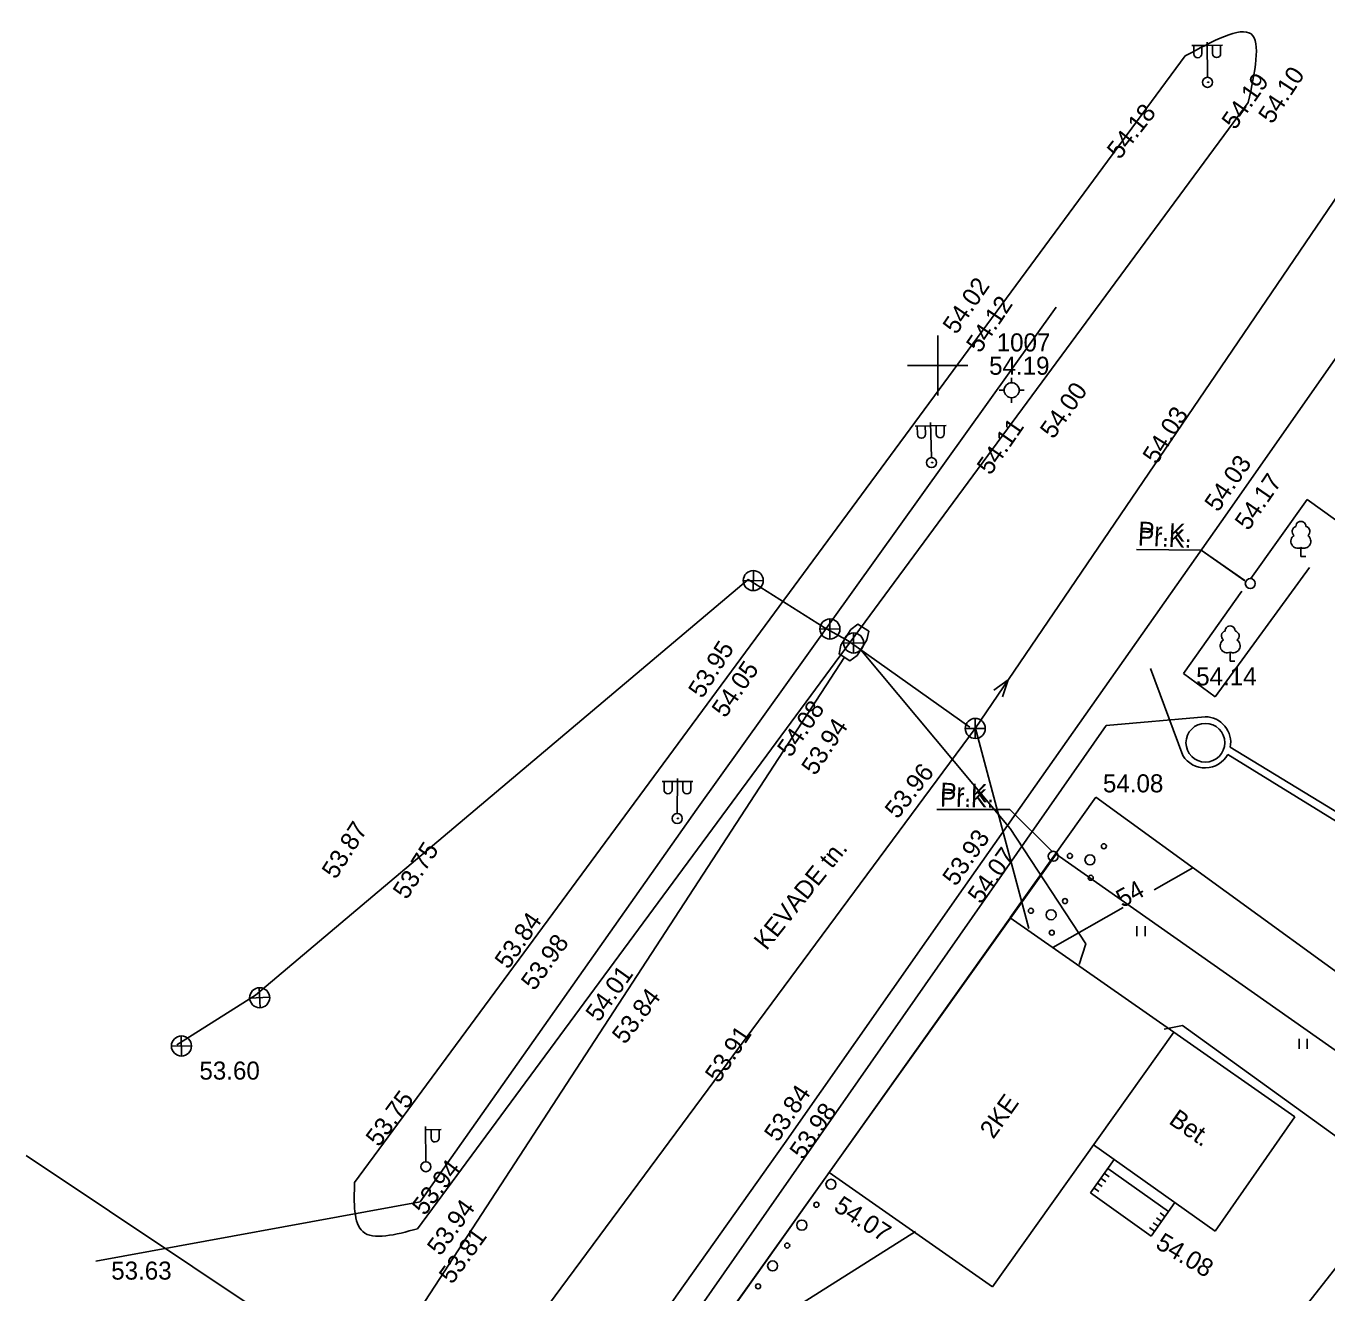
# Model space of a CAD drawing. Extents: x -2270 to -2134, y 846 to 969.
# Drawn here: x -2257.8 to -2193, y 905.3 to 968.5 of the extents above; entities that cross this region are included whole.
import ezdxf

# ---------------------------------------------------------------- set-up
doc = ezdxf.new("R2010")
doc.units = 0
for name, color, linetype in [('Level 11', 7, 'Continuous'), ('Level 12', 7, 'Continuous'), ('Level 15', 7, 'Continuous'), ('Level 16', 7, 'Continuous'), ('Level 18', 7, 'Continuous'), ('Level 19', 7, 'Continuous'), ('Level 21', 7, 'Continuous'), ('Level 29', 7, 'Continuous'), ('Level 31', 7, 'Continuous'), ('Level 32', 7, 'Continuous'), ('Level 4', 7, 'Continuous'), ('Level 45', 7, 'Continuous'), ('Level 6', 7, 'Continuous'), ('Level 7', 7, 'Continuous'), ('Level 8', 7, 'Continuous'), ('Level 9', 7, 'Continuous')]:
    doc.layers.add(name, color=color, linetype=linetype)

msp = doc.modelspace()

# ---------------------------------------------------------------- linework, layer by layer
at = {"layer": 'Level 11'}
for p, q in [((-2221.556, 941.341), (-2221.573, 940.341)), ((-2222.064, 940.85), (-2221.065, 940.832)), ((-2217.74, 938.926), (-2217.746, 937.926)), ((-2218.243, 938.429), (-2217.243, 938.423)), ((-2216.562, 938.229), (-2216.565, 937.229)), ((-2217.063, 937.731), (-2216.063, 937.727)), ((-2210.494, 933.965), (-2210.495, 932.965)), ((-2210.994, 933.466), (-2209.994, 933.464)), ((-2246.205, 920.534), (-2246.152, 919.536)), ((-2246.678, 920.009), (-2245.679, 920.062)), ((-2250.086, 918.127), (-2250.071, 917.127)), ((-2250.578, 917.62), (-2249.579, 917.634))]:
    msp.add_line(p, q, dxfattribs=at)
for centre in [(-2221.564, 940.841), (-2217.743, 938.426), (-2216.563, 937.729), (-2210.494, 933.465), (-2246.178, 920.035), (-2250.078, 917.627)]:
    msp.add_circle(centre, 0.5, dxfattribs=at)
at = {"layer": 'Level 12'}
for p, q in [((-2198.893, 965.701), (-2198.916, 965.696)), ((-2198.914, 965.686), (-2198.916, 965.696)), ((-2198.856, 965.72), (-2198.895, 965.711)), ((-2198.895, 965.711), (-2198.891, 965.692)), ((-2198.852, 965.7), (-2198.891, 965.692)), ((-2198.856, 965.72), (-2198.852, 965.7)), ((-2212.654, 946.731), (-2212.677, 946.725)), ((-2212.675, 946.715), (-2212.677, 946.725)), ((-2212.617, 946.75), (-2212.656, 946.74)), ((-2212.656, 946.74), (-2212.652, 946.721)), ((-2212.613, 946.73), (-2212.652, 946.721)), ((-2212.617, 946.75), (-2212.613, 946.73)), ((-2199.231, 942.365), (-2202.455, 942.392)), ((-2197.055, 940.837), (-2199.231, 942.365)), ((-2225.331, 928.98), (-2225.354, 928.975)), ((-2225.352, 928.965), (-2225.354, 928.975)), ((-2225.293, 928.998), (-2225.333, 928.99)), ((-2225.333, 928.99), (-2225.329, 928.97)), ((-2225.289, 928.978), (-2225.329, 928.97)), ((-2225.293, 928.998), (-2225.289, 928.978)), ((-2208.772, 929.43), (-2212.416, 929.43)), ((-2206.655, 927.334), (-2208.772, 929.43)), ((-2237.905, 913.605), (-2237.89, 911.855)), ((-2237.903, 913.448), (-2237.135, 913.454)), ((-2237.632, 913.451), (-2237.629, 913.036)), ((-2237.232, 913.453), (-2237.229, 913.04))]:
    msp.add_line(p, q, dxfattribs=at)
for centre in [(-2196.782, 940.691), (-2206.607, 927.089), (-2237.888, 911.605)]:
    msp.add_circle(centre, 0.25, dxfattribs=at)
msp.add_arc((-2237.429, 913.038), 0.2, 180.45577, 0.45577, dxfattribs=at)
at = {"layer": 'Level 15'}
msp.add_line((-2207.825, 923.49), (-2210.493, 933.535), dxfattribs=at)
for points in [[(-2238.128, 896.128), (-2210.494, 933.465), (-2189.567, 964.235)], [(-2209.567, 935.379), (-2208.851, 935.896), (-2209.13, 935.041)]]:
    msp.add_lwpolyline(points, dxfattribs=at)
at = {"layer": 'Level 16'}
for p, q in [((-2212.369, 953.074), (-2212.369, 950.074)), ((-2213.869, 951.574), (-2210.869, 951.574)), ((-2208.681, 950.961), (-2208.681, 950.711)), ((-2209.306, 950.336), (-2209.056, 950.336)), ((-2208.681, 949.961), (-2208.681, 949.711)), ((-2208.306, 950.336), (-2208.056, 950.336)), ((-2237.916, 892.929), (-2213.477, 908.38))]:
    msp.add_line(p, q, dxfattribs=at)
msp.add_circle((-2208.681, 950.336), 0.375, dxfattribs=at)
at = {"layer": 'Level 18'}
msp.add_line((-2246.733, 891.382), (-2217.016, 937.014), dxfattribs=at)
msp.add_lwpolyline([(-2205.312, 921.696), (-2204.98, 922.729), (-2208.752, 928.473), (-2216.197, 937.392)], dxfattribs=at)
at = {"layer": 'Level 19'}
for p, q in [((-2200.024, 967.013), (-2241.447, 910.825)), ((-2196.881, 964.696), (-2238.304, 908.508)), ((-2185.903, 961.405), (-2197.926, 944.224)), ((-2197.926, 944.224), (-2211.091, 925.475)), ((-2200.146, 932.114), (-2201.752, 936.449)), ((-2230.178, 896.053), (-2203.961, 933.613)), ((-2203.961, 933.613), (-2199.031, 934.048)), ((-2211.091, 925.475), (-2220.006, 912.755)), ((-2220.006, 912.755), (-2232.856, 894.697)), ((-2232.804, 895.458), (-2257.828, 912.171))]:
    msp.add_line(p, q, dxfattribs=at)
for points in [[(-2197.783, 932.526), (-2180.783, 922.176), (-2171.133, 931.391), (-2166.861, 928.633)], [(-2197.901, 932.165), (-2180.774, 921.614), (-2171.008, 930.85), (-2167.125, 928.209)]]:
    msp.add_lwpolyline(points, dxfattribs=at)
msp.add_circle((-2199.022, 932.755), 0.966, dxfattribs=at)
for centre, radius, start, end in [((-2199.038, 932.77), 1.279, 348.99678, 89.69052), ((-2199.039, 932.805), 1.305, 211.96214, 330.64357)]:
    msp.add_arc(centre, radius, start, end, dxfattribs=at)
for points in [[(-2200.024, 967.013), (-2196.743, 968.107), (-2196.881, 964.696)], [(-2241.447, 910.825), (-2241.036, 908.365), (-2238.304, 908.508)]]:
    msp.add_spline(points, degree=3, dxfattribs=at)
at = {"layer": 'Level 21'}
for p, q in [((-2224.379, 929.446), (-2206.468, 954.486)), ((-2238.17, 909.855), (-2224.379, 929.446)), ((-2200.158, 918.652), (-2201.075, 918.46)), ((-2189.64, 911.045), (-2200.158, 918.652)), ((-2208.173, 886.648), (-2189.276, 910.702)), ((-2254.351, 906.888), (-2238.17, 909.855))]:
    msp.add_line(p, q, dxfattribs=at)
at = {"layer": 'Level 29'}
msp.add_line((-2216.836, 937.839), (-2210.772, 933.534), dxfattribs=at)
msp.add_lwpolyline([(-2250.314, 917.68), (-2246.382, 920.16), (-2221.812, 940.896), (-2218.033, 938.498), (-2216.836, 937.839)], dxfattribs=at)
at = {"layer": 'Level 31'}
msp.add_lwpolyline([(-2215.809, 938.321), (-2215.899, 937.885), (-2216.392, 937.11), (-2216.747, 936.843), (-2217.284, 937.184), (-2217.194, 937.619), (-2216.701, 938.395), (-2216.346, 938.661)], close=True, dxfattribs=at)
at = {"layer": 'Level 32'}
for p, q in [((-2199.64, 926.521), (-2201.567, 925.422)), ((-2203.125, 924.535), (-2206.628, 922.538))]:
    msp.add_line(p, q, dxfattribs=at)
at = {"layer": 'Level 45'}
for p, q in [((-2230.947, 892.878), (-2206.455, 927.192)), ((-2206.455, 927.192), (-2182.404, 910.289))]:
    msp.add_line(p, q, dxfattribs=at)
at = {"layer": 'Level 6'}
for p, q in [((-2208.75, 924.023), (-2217.784, 911.32)), ((-2208.75, 924.023), (-2217.784, 911.32)), ((-2208.75, 924.023), (-2200.602, 918.32)), ((-2200.602, 918.32), (-2209.636, 905.617)), ((-2194.555, 914.088), (-2200.602, 918.32)), ((-2198.54, 908.394), (-2194.555, 914.088)), ((-2198.54, 908.394), (-2204.598, 912.702)), ((-2204.756, 910.298), (-2203.567, 911.969)), ((-2200.861, 909.369), (-2203.887, 911.521)), ((-2217.784, 911.32), (-2209.636, 905.617)), ((-2204.164, 910.613), (-2204.408, 910.787)), ((-2203.99, 910.858), (-2204.234, 911.032)), ((-2203.816, 911.102), (-2204.061, 911.276)), ((-2201.73, 908.146), (-2204.756, 910.298)), ((-2204.338, 910.369), (-2204.582, 910.543)), ((-2201.73, 908.146), (-2200.542, 909.818)), ((-2201.209, 908.88), (-2201.453, 909.054)), ((-2201.035, 909.124), (-2201.279, 909.298)), ((-2201.556, 908.391), (-2201.801, 908.565)), ((-2201.383, 908.635), (-2201.627, 908.809))]:
    msp.add_line(p, q, dxfattribs=at)
at = {"layer": 'Level 7'}
for p, q in [((-2193.951, 944.887), (-2196.753, 940.942)), ((-2192.525, 943.875), (-2193.951, 944.887)), ((-2193.833, 941.5), (-2198.527, 935.041)), ((-2197.202, 940.31), (-2200.12, 936.199)), ((-2200.12, 936.199), (-2198.527, 935.041)), ((-2204.489, 930.045), (-2208.76, 924.03)), ((-2183.528, 914.813), (-2204.489, 930.045)), ((-2217.784, 911.32), (-2231.76, 891.681))]:
    msp.add_line(p, q, dxfattribs=at)
at = {"layer": 'Level 8'}
for p, q in [((-2198.934, 967.539), (-2199.703, 967.532)), ((-2199.604, 967.533), (-2199.6, 967.119)), ((-2199.204, 967.537), (-2199.2, 967.122)), ((-2198.935, 967.696), (-2198.919, 965.946)), ((-2198.934, 967.539), (-2198.165, 967.546)), ((-2198.663, 967.542), (-2198.66, 967.127)), ((-2198.263, 967.545), (-2198.26, 967.131)), ((-2212.721, 948.568), (-2213.49, 948.549)), ((-2213.392, 948.552), (-2213.382, 948.138)), ((-2212.992, 948.561), (-2212.982, 948.147)), ((-2212.725, 948.725), (-2212.683, 946.975)), ((-2212.721, 948.568), (-2211.953, 948.586)), ((-2212.451, 948.574), (-2212.441, 948.16)), ((-2212.051, 948.584), (-2212.041, 948.169)), ((-2199.231, 942.366), (-2202.455, 942.392)), ((-2197.055, 940.838), (-2199.231, 942.366)), ((-2225.343, 930.975), (-2225.353, 929.225)), ((-2225.344, 930.818), (-2226.112, 930.823)), ((-2226.014, 930.822), (-2226.016, 930.408)), ((-2225.614, 930.82), (-2225.616, 930.405)), ((-2225.344, 930.818), (-2224.575, 930.814)), ((-2225.073, 930.817), (-2225.075, 930.402)), ((-2224.673, 930.814), (-2224.675, 930.4)), ((-2208.772, 929.431), (-2212.417, 929.431)), ((-2206.655, 927.335), (-2208.772, 929.431)), ((-2237.904, 913.605), (-2237.89, 911.855)), ((-2237.903, 913.448), (-2237.134, 913.454)), ((-2237.633, 913.45), (-2237.629, 913.036)), ((-2237.233, 913.453), (-2237.229, 913.039))]:
    msp.add_line(p, q, dxfattribs=at)
for centre in [(-2198.916, 965.696), (-2212.677, 946.725), (-2196.782, 940.691), (-2225.354, 928.975), (-2206.607, 927.089), (-2237.888, 911.605)]:
    msp.add_circle(centre, 0.25, dxfattribs=at)
for centre, start, end in [((-2199.4, 967.12), 180.54216, 0.54216), ((-2198.46, 967.129), 180.54216, 0.54216), ((-2213.182, 948.142), 181.36607, 1.36607), ((-2212.241, 948.165), 181.36607, 1.36607), ((-2225.816, 930.407), 179.6594, 359.6594), ((-2224.876, 930.401), 179.6594, 359.6594), ((-2237.429, 913.038), 180.4559, 0.4559)]:
    msp.add_arc(centre, 0.2, start, end, dxfattribs=at)
at = {"layer": 'Level 9'}
for p, q in [((-2194.26, 942.483), (-2194.26, 942.043)), ((-2194.26, 942.043), (-2194.02, 942.043)), ((-2197.787, 937.269), (-2197.787, 936.829)), ((-2197.787, 936.829), (-2197.547, 936.829)), ((-2202.432, 923.097), (-2202.432, 923.597)), ((-2202.032, 923.097), (-2202.032, 923.597)), ((-2194.346, 917.491), (-2194.346, 917.991)), ((-2193.946, 917.491), (-2193.946, 917.991)), ((-2217.691, 910.727), (-2217.691, 910.727))]:
    msp.add_line(p, q, dxfattribs=at)
for centre, radius in [((-2204.082, 927.591), 0.125), ((-2205.779, 927.109), 0.125), ((-2204.776, 926.911), 0.25), ((-2204.74, 926.017), 0.125), ((-2207.719, 924.371), 0.125), ((-2206.715, 924.173), 0.25), ((-2206.022, 924.854), 0.125), ((-2206.679, 923.28), 0.125), ((-2217.691, 910.727), 0.25), ((-2218.418, 909.709), 0.125), ((-2219.145, 908.691), 0.25), ((-2219.872, 907.673), 0.125), ((-2220.599, 906.655), 0.25), ((-2221.326, 905.638), 0.125)]:
    msp.add_circle(centre, radius, dxfattribs=at)
for centre, radius, start, end in [((-2194.446, 943.298), 0.25, 104.88012, 233.15525), ((-2194.26, 943.543), 0.25, 359.8604, 180.8406), ((-2194.062, 943.298), 0.25, 304.57036, 78.15304), ((-2194.41, 942.802), 0.35, 122.21649, 294.84737), ((-2194.115, 942.802), 0.35, 245.15263, 56.0466), ((-2197.973, 938.084), 0.25, 104.88012, 233.15525), ((-2197.787, 938.329), 0.25, 359.8604, 180.8406), ((-2197.589, 938.084), 0.25, 304.57036, 78.15304), ((-2197.937, 937.588), 0.35, 122.21649, 294.84737), ((-2197.642, 937.588), 0.35, 245.15263, 56.0466)]:
    msp.add_arc(centre, radius, start, end, dxfattribs=at)

# ---------------------------------------------------------------- texts
at = {"layer": 'Level 12'}
for height, rotation, p in [(0.899, 357, (-2202.385, 942.895)), (0.9, 358, (-2212.248, 929.865))]:
    msp.add_text('Pr.K.', height=height, rotation=rotation, dxfattribs=at).set_placement(p)
at = {"layer": 'Level 16'}
for s, p in [('1007', (-2209.428, 952.273)), ('54.19', (-2209.806, 951.109))]:
    msp.add_text(s, height=0.9, dxfattribs=at).set_placement(p)
at = {"layer": 'Level 32'}
msp.add_text('54', height=0.9, rotation=29, dxfattribs=at).set_placement((-2203.153, 924.502))
at = {"layer": 'Level 4'}
for s, height, rotation, p in [('54.19', 0.9, 54.91044, (-2197.542, 963.282)), ('54.10', 0.9, 56.5317, (-2195.694, 963.572)), ('54.18', 0.9, 51.83446, (-2203.298, 961.801)), ('54.02', 0.9, 55.52762, (-2211.441, 953.073)), ('54.12', 0.8995, 56.16997, (-2210.263, 952.144)), ('54.00', 0.8995, 54.73031, (-2206.6, 947.86)), ('54.03', 0.9, 57.77753, (-2201.449, 946.599)), ('54.11', 0.9, 55.17609, (-2209.743, 946.055)), ('54.03', 0.9, 55.52881, (-2198.388, 944.215)), ('54.17', 0.9, 55.52763, (-2196.876, 943.287)), ('53.95', 0.9, 57.54569, (-2224.105, 934.916)), ('54.05', 0.9, 55.38593, (-2222.961, 933.946)), ('54.08', 0.9, 55.0562, (-2219.7, 931.979)), ('53.94', 0.9, 56.20802, (-2218.479, 931.07)), ('53.96', 0.9, 51.61535, (-2214.376, 928.904)), ('53.87', 0.9, 57.29964, (-2242.384, 925.901)), ('53.93', 0.9, 54.92832, (-2211.463, 925.549)), ('53.75', 0.9, 57.33678, (-2238.84, 924.886)), ('54.07', 0.9, 54.20859, (-2210.211, 924.661)), ('53.84', 0.9, 55.22443, (-2233.787, 921.41)), ('53.98', 0.9, 54.16201, (-2232.484, 920.341)), ('54.01', 0.9, 54.41267, (-2229.262, 918.771)), ('53.84', 0.9, 52.68041, (-2227.965, 917.664)), ('53.91', 0.9, 56.14984, (-2223.286, 915.733)), ('53.75', 0.8995, 53.5757, (-2240.234, 912.549)), ('53.84', 0.9, 56.17435, (-2220.336, 912.786)), ('53.98', 0.9, 55.23234, (-2219.081, 911.905)), ('53.94', 0.9, 52.34305, (-2237.952, 909.121)), ('54.07', 0.9, 326.96624, (-2217.609, 909.45)), ('53.94', 0.9, 53.86821, (-2237.171, 907.112)), ('53.81', 0.9, 53.89865, (-2236.581, 905.699)), ('54.08', 0.9, 329.25499, (-2201.563, 907.584))]:
    msp.add_text(s, height=height, rotation=rotation, dxfattribs=at).set_placement(p)
for s, p in [('54.14', (-2199.48, 935.611)), ('54.08', (-2204.129, 930.278)), ('53.60', (-2249.182, 915.95)), ('53.63', (-2253.579, 905.973))]:
    msp.add_text(s, height=0.9, dxfattribs=at).set_placement(p)
at = {"layer": 'Level 6'}
for s, rotation, p in [('2KE', 54.58068, (-2209.599, 912.945)), ('Bet.', 325.01081, (-2200.896, 913.793))]:
    msp.add_text(s, height=0.9, rotation=rotation, dxfattribs=at).set_placement(p)
at = {"layer": 'Level 7'}
msp.add_text('KEVADE tn.', height=0.9, rotation=51.35448, dxfattribs=at).set_placement((-2220.906, 922.353))
at = {"layer": 'Level 8'}
for height, rotation, p in [(0.8995, 357.29521, (-2202.401, 942.596)), (0.9, 358.96728, (-2212.258, 929.565))]:
    msp.add_text('Pr.K.', height=height, rotation=rotation, dxfattribs=at).set_placement(p)

doc.saveas('drawing.dxf')
